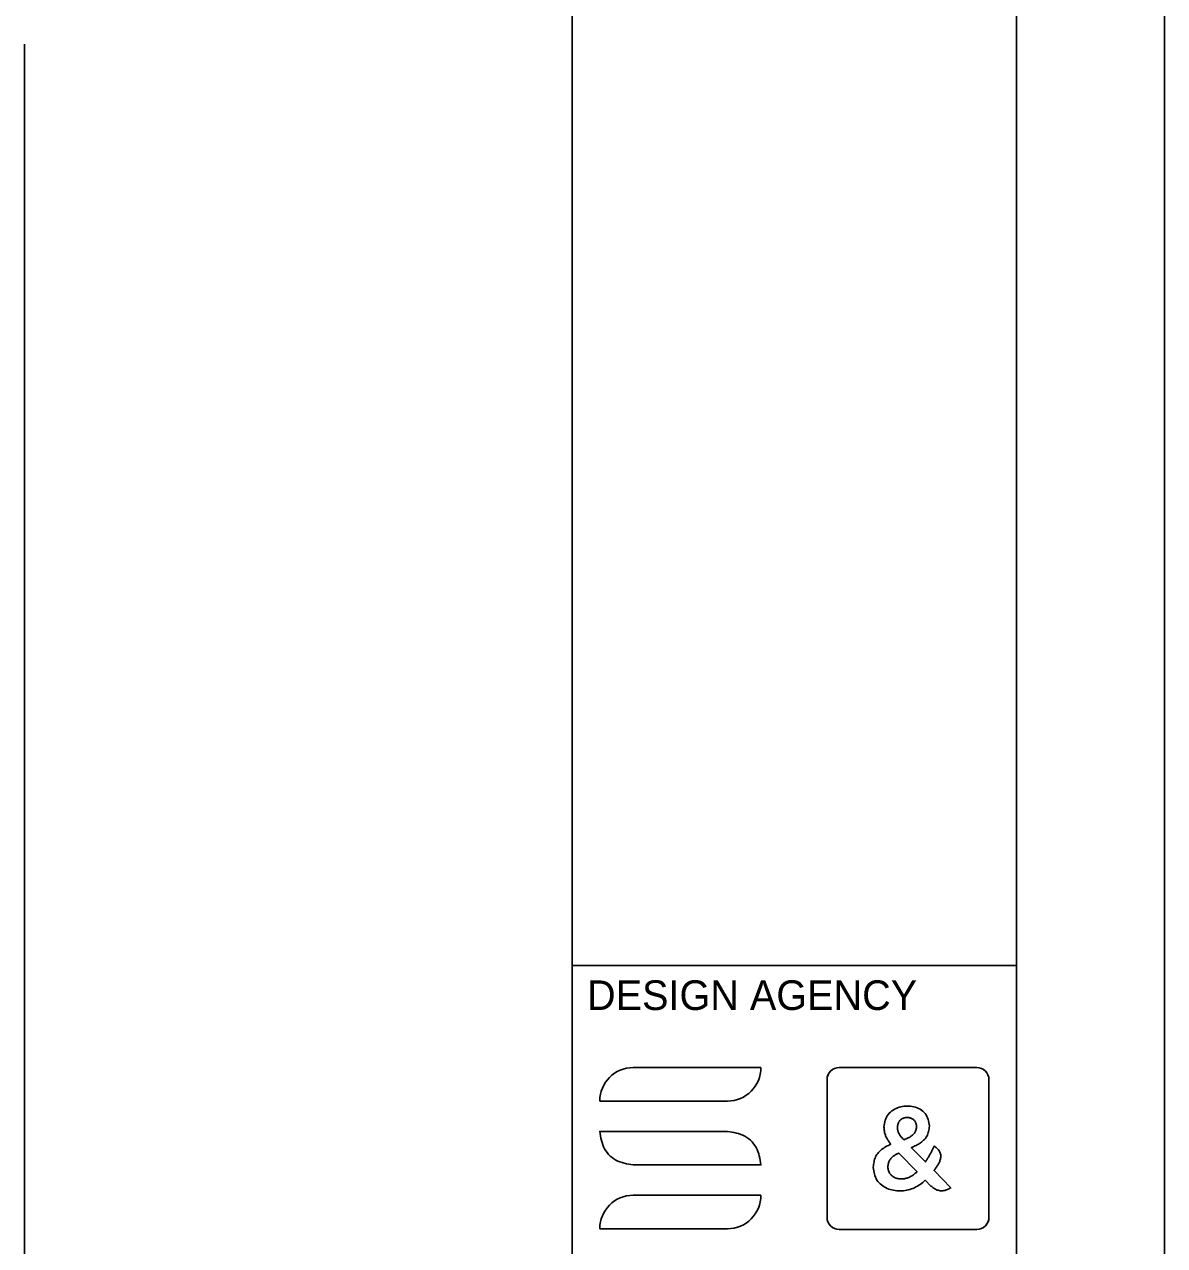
# Model space of a CAD drawing. Extents: x -2280229 to 1306, y -58886 to 440.
# Drawn here: x 603 to 680, y 81.1 to 163.6 of the extents above; entities that cross this region are included whole.
import ezdxf

# ---------------------------------------------------------------- set-up
doc = ezdxf.new("R2010")
doc.units = 0
for name, color, linetype in [('GT_Project_Cells', 7, 'Continuous'), ('GT_Project_Soil_Boring', 7, 'Continuous'), ('GT_Project_Text', 7, 'Continuous'), ('SC_Scratch1', 7, 'Continuous'), ('SC_Scratch5', 7, 'Continuous')]:
    doc.layers.add(name, color=color, linetype=linetype)

msp = doc.modelspace()

# ---------------------------------------------------------------- linework, layer by layer
at = {"layer": 'GT_Project_Soil_Boring'}
for p, q in [((667.315, 93.113), (658.028, 93.113)), ((657.209, 92.294), (657.209, 82.998)), ((668.143, 83.01), (668.143, 92.294)), ((661.968, 89.124), (661.962, 89.074)), ((661.962, 89.074), (661.962, 89.058)), ((661.975, 89.175), (661.968, 89.124)), ((661.983, 89.224), (661.975, 89.175)), ((661.993, 89.273), (661.983, 89.224)), ((662.005, 89.321), (661.993, 89.273)), ((662.021, 89.367), (662.005, 89.321)), ((662.04, 89.412), (662.021, 89.367)), ((662.064, 89.455), (662.04, 89.412)), ((662.093, 89.496), (662.064, 89.455)), ((662.125, 89.535), (662.093, 89.496)), ((662.16, 89.571), (662.125, 89.535)), ((662.198, 89.604), (662.16, 89.571)), ((662.239, 89.634), (662.198, 89.604)), ((662.282, 89.66), (662.239, 89.634)), ((662.327, 89.682), (662.282, 89.66)), ((662.374, 89.7), (662.327, 89.682)), ((662.422, 89.715), (662.374, 89.7)), ((662.47, 89.727), (662.422, 89.715)), ((662.52, 89.735), (662.47, 89.727)), ((662.57, 89.739), (662.52, 89.735)), ((662.62, 89.741), (662.57, 89.739)), ((662.67, 89.739), (662.62, 89.741)), ((662.72, 89.734), (662.67, 89.739)), ((662.769, 89.726), (662.72, 89.734)), ((662.818, 89.715), (662.769, 89.726)), ((662.865, 89.7), (662.818, 89.715)), ((662.912, 89.681), (662.865, 89.7)), ((662.956, 89.658), (662.912, 89.681)), ((662.999, 89.631), (662.956, 89.658)), ((663.04, 89.601), (662.999, 89.631)), ((663.078, 89.567), (663.04, 89.601)), ((663.112, 89.531), (663.078, 89.567)), ((663.143, 89.491), (663.112, 89.531)), ((663.169, 89.45), (663.143, 89.491)), ((663.191, 89.406), (663.169, 89.45)), ((663.208, 89.36), (663.191, 89.406)), ((663.222, 89.312), (663.208, 89.36)), ((663.233, 89.264), (663.222, 89.312)), ((663.241, 89.214), (663.233, 89.264)), ((663.248, 89.164), (663.241, 89.214)), ((663.245, 89.04), (663.255, 89.098)), ((663.255, 89.114), (663.248, 89.164)), ((663.255, 89.098), (663.255, 89.114)), ((661.962, 89.058), (661.965, 89.017)), ((661.965, 89.017), (661.969, 88.975)), ((661.969, 88.975), (661.974, 88.934)), ((661.974, 88.934), (661.98, 88.893)), ((661.98, 88.893), (661.988, 88.853)), ((661.988, 88.853), (661.997, 88.813)), ((661.997, 88.813), (662.009, 88.774)), ((662.009, 88.774), (662.024, 88.736)), ((662.024, 88.736), (662.04, 88.698)), ((662.04, 88.698), (662.059, 88.661)), ((662.059, 88.661), (662.079, 88.625)), ((662.079, 88.625), (662.101, 88.589)), ((662.101, 88.589), (662.124, 88.554)), ((662.124, 88.554), (662.147, 88.52)), ((662.147, 88.52), (662.172, 88.487)), ((662.172, 88.487), (662.197, 88.454)), ((662.197, 88.454), (662.222, 88.421)), ((662.222, 88.421), (662.248, 88.389)), ((662.248, 88.389), (662.274, 88.358)), ((662.274, 88.358), (662.328, 88.295)), ((662.328, 88.295), (662.382, 88.233)), ((662.382, 88.233), (662.487, 88.275)), ((662.487, 88.275), (662.539, 88.297)), ((662.539, 88.297), (662.591, 88.32)), ((662.591, 88.32), (662.643, 88.343)), ((662.643, 88.343), (662.694, 88.367)), ((662.694, 88.367), (662.745, 88.393)), ((662.745, 88.393), (662.795, 88.421)), ((662.795, 88.421), (662.845, 88.45)), ((662.845, 88.45), (662.894, 88.481)), ((662.894, 88.481), (662.942, 88.515)), ((662.942, 88.515), (662.988, 88.551)), ((662.988, 88.551), (663.031, 88.589)), ((663.031, 88.589), (663.072, 88.629)), ((663.072, 88.629), (663.109, 88.673)), ((663.109, 88.673), (663.141, 88.718)), ((663.141, 88.718), (663.168, 88.767)), ((663.168, 88.767), (663.19, 88.818)), ((663.19, 88.818), (663.208, 88.872)), ((663.208, 88.872), (663.223, 88.927)), ((663.223, 88.927), (663.235, 88.983)), ((663.235, 88.983), (663.245, 89.04)), ((661.346, 86.632), (661.335, 86.578)), ((661.359, 86.684), (661.346, 86.632)), ((661.376, 86.735), (661.359, 86.684)), ((661.397, 86.785), (661.376, 86.735)), ((661.421, 86.833), (661.397, 86.785)), ((661.45, 86.879), (661.421, 86.833)), ((661.481, 86.924), (661.45, 86.879)), ((661.516, 86.966), (661.481, 86.924)), ((661.553, 87.007), (661.516, 86.966)), ((661.592, 87.046), (661.553, 87.007)), ((661.633, 87.082), (661.592, 87.046)), ((661.675, 87.116), (661.633, 87.082)), ((661.719, 87.148), (661.675, 87.116)), ((661.764, 87.178), (661.719, 87.148)), ((661.81, 87.207), (661.764, 87.178)), ((661.857, 87.234), (661.81, 87.207)), ((661.904, 87.261), (661.857, 87.234)), ((661.952, 87.286), (661.904, 87.261)), ((662.001, 87.311), (661.952, 87.286)), ((662.049, 87.336), (662.001, 87.311)), ((663.287, 86.075), (662.049, 87.336)), ((661.318, 86.47), (661.311, 86.416)), ((661.311, 86.416), (661.311, 86.4)), ((661.311, 86.4), (661.321, 86.337)), ((661.326, 86.525), (661.318, 86.47)), ((661.321, 86.337), (661.333, 86.274)), ((661.335, 86.578), (661.326, 86.525)), ((661.333, 86.274), (661.345, 86.213)), ((661.345, 86.213), (661.361, 86.152)), ((661.361, 86.152), (661.38, 86.093)), ((661.38, 86.093), (661.403, 86.037)), ((661.403, 86.037), (661.431, 85.983)), ((661.431, 85.983), (661.465, 85.932)), ((661.465, 85.932), (661.504, 85.884)), ((661.504, 85.884), (661.548, 85.84)), ((661.548, 85.84), (661.596, 85.799)), ((661.596, 85.799), (661.647, 85.761)), ((662.838, 85.744), (662.893, 85.774)), ((662.893, 85.774), (662.946, 85.807)), ((662.946, 85.807), (662.997, 85.841)), ((662.997, 85.841), (663.048, 85.877)), ((663.048, 85.877), (663.097, 85.915)), ((663.097, 85.915), (663.145, 85.954)), ((663.145, 85.954), (663.193, 85.993)), ((663.193, 85.993), (663.24, 86.034)), ((663.24, 86.034), (663.287, 86.075)), ((661.647, 85.761), (661.701, 85.727)), ((661.701, 85.727), (661.757, 85.697)), ((661.757, 85.697), (661.815, 85.671)), ((661.815, 85.671), (661.874, 85.649)), ((661.874, 85.649), (661.933, 85.63)), ((661.933, 85.63), (661.994, 85.615)), ((661.994, 85.615), (662.055, 85.604)), ((662.055, 85.604), (662.117, 85.596)), ((662.117, 85.596), (662.179, 85.592)), ((662.179, 85.592), (662.242, 85.591)), ((662.242, 85.591), (662.304, 85.593)), ((662.304, 85.593), (662.366, 85.598)), ((662.366, 85.598), (662.427, 85.606)), ((662.427, 85.606), (662.488, 85.617)), ((662.488, 85.617), (662.549, 85.632)), ((662.549, 85.632), (662.609, 85.649)), ((662.609, 85.649), (662.668, 85.669)), ((662.668, 85.669), (662.726, 85.691)), ((662.726, 85.691), (662.783, 85.717)), ((662.783, 85.717), (662.838, 85.744)), ((658.028, 82.179), (667.32, 82.179))]:
    msp.add_line(p, q, dxfattribs=at)
for points in [[(652.745, 93.113), (644.121, 93.113)], [(657.572, 92.974), (657.556, 92.964), (657.51, 92.931), (657.467, 92.894), (657.427, 92.854), (657.39, 92.811), (657.357, 92.766), (657.347, 92.749)], [(667.32, 93.113), (658.028, 93.113)], [(668.048, 92.668), (668.048, 92.668), (668.023, 92.718), (667.994, 92.765), (667.961, 92.811), (667.924, 92.854), (667.884, 92.894), (667.841, 92.931), (667.795, 92.964), (667.748, 92.994), (667.733, 93.001)], [(657.209, 92.294), (657.209, 82.998)], [(668.143, 82.998), (668.143, 92.294)], [(641.857, 90.849), (650.481, 90.849)], [(661.767, 90.302), (661.869, 90.353), (661.972, 90.396), (662.078, 90.432), (662.186, 90.461), (662.296, 90.483), (662.406, 90.499), (662.518, 90.508), (662.63, 90.511), (662.742, 90.507), (662.853, 90.498), (662.964, 90.481), (663.073, 90.458), (663.18, 90.428), (663.285, 90.39), (663.388, 90.344), (663.487, 90.29), (663.583, 90.228), (663.672, 90.158), (663.755, 90.082), (663.83, 89.999), (663.896, 89.909), (663.951, 89.815), (663.996, 89.715), (664.031, 89.611), (664.06, 89.503), (664.083, 89.393), (664.102, 89.282), (664.121, 89.162), (664.108, 89.064), (664.096, 88.976), (664.081, 88.888), (664.064, 88.801), (664.043, 88.717), (664.017, 88.634), (663.985, 88.553), (663.946, 88.476), (663.9, 88.402), (663.848, 88.331), (663.791, 88.263), (663.729, 88.199), (663.663, 88.139), (663.593, 88.083), (663.522, 88.03), (663.448, 87.981), (663.372, 87.936), (663.295, 87.894), (663.217, 87.854), (663.138, 87.816), (663.059, 87.78), (662.978, 87.744), (662.898, 87.709), (663.85, 86.741), (663.879, 86.786), (663.908, 86.831), (663.937, 86.876), (663.965, 86.921), (663.994, 86.966), (664.022, 87.011), (664.049, 87.057), (664.077, 87.103), (664.103, 87.149), (664.13, 87.195), (664.156, 87.242), (664.181, 87.289), (664.207, 87.336), (664.232, 87.383), (664.256, 87.43), (664.281, 87.477), (664.305, 87.525), (664.328, 87.573), (664.352, 87.621), (664.376, 87.668), (664.399, 87.716), (664.422, 87.764), (664.445, 87.812), (664.492, 87.777), (664.538, 87.742), (664.583, 87.706), (664.627, 87.669), (664.669, 87.629), (664.708, 87.588), (664.744, 87.544), (664.777, 87.497), (664.806, 87.448), (664.831, 87.395), (664.852, 87.34), (664.868, 87.284), (664.88, 87.227), (664.887, 87.169), (664.889, 87.112), (664.886, 87.055), (664.878, 86.998), (664.867, 86.943), (664.852, 86.887), (664.834, 86.833), (664.814, 86.778), (664.793, 86.724), (664.772, 86.669), (664.758, 86.647), (664.735, 86.61), (664.707, 86.565), (664.679, 86.52), (664.651, 86.475), (664.621, 86.43), (664.592, 86.385), (664.562, 86.341), (664.532, 86.297), (664.501, 86.254), (664.47, 86.211), (664.445, 86.176), (664.43, 86.154), (665.559, 84.985), (665.502, 84.956), (665.445, 84.927), (665.388, 84.9), (665.33, 84.874), (665.272, 84.851), (665.212, 84.83), (665.152, 84.814), (665.09, 84.801), (665.027, 84.793), (664.963, 84.79), (664.899, 84.791), (664.835, 84.797), (664.772, 84.808), (664.71, 84.823), (664.649, 84.842), (664.591, 84.865), (664.534, 84.893), (664.48, 84.924), (664.426, 84.957), (664.374, 84.993), (664.323, 85.031), (664.272, 85.07), (664.222, 85.109), (663.842, 85.503), (663.757, 85.431), (663.671, 85.36), (663.584, 85.291), (663.495, 85.224), (663.404, 85.161), (663.31, 85.101), (663.213, 85.047), (663.113, 84.997), (663.011, 84.952), (662.906, 84.912), (662.8, 84.878), (662.692, 84.848), (662.583, 84.825), (662.473, 84.806), (662.363, 84.793), (662.251, 84.784), (662.14, 84.781), (662.028, 84.783), (661.916, 84.79), (661.805, 84.803), (661.695, 84.821), (661.586, 84.845), (661.478, 84.875), (661.371, 84.91), (661.266, 84.953), (661.164, 85.002), (661.063, 85.057), (660.967, 85.119), (660.875, 85.186), (660.79, 85.26), (660.71, 85.34), (660.639, 85.425), (660.576, 85.515), (660.523, 85.61), (660.478, 85.71), (660.441, 85.814), (660.411, 85.921), (660.385, 86.03), (660.364, 86.142), (660.345, 86.255), (660.326, 86.375), (660.337, 86.475), (660.349, 86.566), (660.362, 86.656), (660.378, 86.745), (660.398, 86.832), (660.422, 86.918), (660.452, 87.003), (660.488, 87.084), (660.531, 87.164), (660.579, 87.24), (660.633, 87.313), (660.692, 87.383), (660.754, 87.45), (660.821, 87.513), (660.89, 87.571), (660.962, 87.626), (661.036, 87.677), (661.112, 87.726), (661.189, 87.771), (661.268, 87.815), (661.348, 87.857), (661.428, 87.899), (661.509, 87.939), (661.477, 87.984), (661.444, 88.029), (661.412, 88.074), (661.381, 88.119), (661.35, 88.165), (661.32, 88.211), (661.29, 88.258), (661.262, 88.306), (661.236, 88.354), (661.21, 88.403), (661.186, 88.454), (661.164, 88.504), (661.144, 88.556), (661.126, 88.608), (661.11, 88.661), (661.096, 88.714), (661.085, 88.768), (661.076, 88.823), (661.068, 88.877), (661.062, 88.932), (661.057, 88.987), (661.053, 89.043), (661.048, 89.109), (661.067, 89.226), (661.087, 89.338), (661.11, 89.448), (661.138, 89.555), (661.173, 89.659), (661.217, 89.76), (661.271, 89.855), (661.334, 89.945), (661.407, 90.029), (661.488, 90.108), (661.576, 90.179), (661.67, 90.244), (661.767, 90.302)], [(652.336, 87.846), (652.245, 87.971), (652.143, 88.09), (652.033, 88.2), (651.915, 88.301), (651.789, 88.393), (651.658, 88.473), (651.522, 88.542), (651.381, 88.599), (651.236, 88.647), (651.089, 88.688), (650.939, 88.721), (650.787, 88.751), (650.634, 88.777), (650.481, 88.801), (641.857, 88.801), (641.882, 88.647), (641.908, 88.494), (641.937, 88.343), (641.971, 88.193), (642.011, 88.045), (642.059, 87.901), (642.117, 87.76), (642.185, 87.624), (642.266, 87.493), (642.357, 87.367), (642.459, 87.249), (642.569, 87.138), (642.687, 87.037), (642.813, 86.946), (642.944, 86.865), (643.08, 86.797), (643.221, 86.739), (643.366, 86.691), (643.513, 86.651), (643.663, 86.617), (643.815, 86.588), (643.968, 86.562), (644.121, 86.537), (652.745, 86.537), (652.72, 86.691), (652.694, 86.844), (652.665, 86.996), (652.631, 87.146), (652.591, 87.293), (652.543, 87.437), (652.485, 87.578), (652.417, 87.714), (652.336, 87.846)], [(652.745, 84.489), (644.121, 84.489)], [(641.857, 82.226), (650.481, 82.226)], [(658.028, 82.179), (667.32, 82.179)]]:
    msp.add_lwpolyline(points, dxfattribs=at)
for points in [[(663.842, 85.503), (663.757, 85.431), (663.671, 85.36), (663.584, 85.291), (663.495, 85.224), (663.404, 85.161), (663.31, 85.101), (663.213, 85.047), (663.113, 84.997), (663.011, 84.952), (662.906, 84.912), (662.8, 84.878), (662.692, 84.848), (662.583, 84.825), (662.473, 84.806), (662.363, 84.793), (662.251, 84.784), (662.14, 84.781), (662.028, 84.783), (661.916, 84.79), (661.805, 84.803), (661.695, 84.821), (661.586, 84.845), (661.478, 84.875), (661.371, 84.91), (661.266, 84.953), (661.164, 85.002), (661.063, 85.057), (660.967, 85.119), (660.875, 85.186), (660.79, 85.26), (660.71, 85.34), (660.639, 85.425), (660.576, 85.515), (660.523, 85.61), (660.478, 85.71), (660.441, 85.814), (660.411, 85.921), (660.385, 86.03), (660.364, 86.142), (660.345, 86.255), (660.327, 86.368), (660.327, 86.384), (660.337, 86.475), (660.349, 86.566), (660.362, 86.656), (660.378, 86.745), (660.398, 86.832), (660.422, 86.918), (660.452, 87.003), (660.488, 87.084), (660.531, 87.164), (660.579, 87.24), (660.633, 87.313), (660.692, 87.383), (660.754, 87.45), (660.821, 87.513), (660.89, 87.571), (660.962, 87.626), (661.036, 87.677), (661.112, 87.726), (661.189, 87.771), (661.268, 87.815), (661.348, 87.857), (661.428, 87.899), (661.509, 87.939), (661.477, 87.984), (661.444, 88.029), (661.412, 88.074), (661.381, 88.119), (661.35, 88.165), (661.32, 88.211), (661.29, 88.258), (661.262, 88.306), (661.236, 88.354), (661.21, 88.403), (661.186, 88.454), (661.164, 88.504), (661.144, 88.556), (661.126, 88.608), (661.11, 88.661), (661.096, 88.714), (661.085, 88.768), (661.076, 88.823), (661.068, 88.877), (661.062, 88.932), (661.057, 88.987), (661.053, 89.043), (661.049, 89.098), (661.049, 89.114), (661.067, 89.226), (661.087, 89.338), (661.11, 89.448), (661.138, 89.555), (661.173, 89.659), (661.217, 89.76), (661.271, 89.855), (661.334, 89.945), (661.407, 90.029), (661.488, 90.108), (661.576, 90.179), (661.67, 90.244), (661.767, 90.302), (661.869, 90.353), (661.972, 90.396), (662.078, 90.432), (662.186, 90.461), (662.296, 90.483), (662.406, 90.499), (662.518, 90.508), (662.63, 90.511), (662.742, 90.507), (662.853, 90.498), (662.964, 90.481), (663.073, 90.458), (663.18, 90.428), (663.285, 90.39), (663.388, 90.344), (663.487, 90.29), (663.583, 90.228), (663.672, 90.158), (663.755, 90.082), (663.83, 89.999), (663.896, 89.909), (663.951, 89.815), (663.996, 89.715), (664.031, 89.611), (664.06, 89.503), (664.083, 89.393), (664.102, 89.282), (664.12, 89.169), (664.12, 89.154), (664.108, 89.064), (664.096, 88.976), (664.081, 88.888), (664.064, 88.801), (664.043, 88.717), (664.017, 88.634), (663.985, 88.553), (663.946, 88.476), (663.9, 88.402), (663.848, 88.331), (663.791, 88.263), (663.729, 88.199), (663.663, 88.139), (663.593, 88.083), (663.522, 88.03), (663.448, 87.981), (663.372, 87.936), (663.295, 87.894), (663.217, 87.854), (663.138, 87.816), (663.059, 87.78), (662.978, 87.744), (662.898, 87.709), (663.85, 86.741), (663.879, 86.786), (663.908, 86.831), (663.937, 86.876), (663.965, 86.921), (663.994, 86.966), (664.022, 87.011), (664.049, 87.057), (664.077, 87.103), (664.103, 87.149), (664.13, 87.195), (664.156, 87.242), (664.181, 87.289), (664.207, 87.336), (664.232, 87.383), (664.256, 87.43), (664.281, 87.477), (664.305, 87.525), (664.328, 87.573), (664.352, 87.621), (664.376, 87.668), (664.399, 87.716), (664.422, 87.764), (664.445, 87.812), (664.492, 87.777), (664.538, 87.742), (664.583, 87.706), (664.627, 87.669), (664.669, 87.629), (664.708, 87.588), (664.744, 87.544), (664.777, 87.497), (664.806, 87.448), (664.831, 87.395), (664.852, 87.34), (664.868, 87.284), (664.88, 87.227), (664.887, 87.169), (664.889, 87.112), (664.886, 87.055), (664.878, 86.998), (664.867, 86.943), (664.852, 86.887), (664.834, 86.833), (664.814, 86.778), (664.793, 86.724), (664.772, 86.669), (664.758, 86.647), (664.744, 86.624), (664.729, 86.601), (664.715, 86.578), (664.701, 86.555), (664.687, 86.532), (664.672, 86.509), (664.658, 86.487), (664.643, 86.464), (664.629, 86.442), (664.614, 86.419), (664.599, 86.397), (664.584, 86.374), (664.569, 86.352), (664.554, 86.33), (664.539, 86.308), (664.523, 86.285), (664.508, 86.263), (664.492, 86.242), (664.477, 86.22), (664.461, 86.198), (664.445, 86.176), (664.43, 86.154), (665.559, 84.985), (665.502, 84.956), (665.445, 84.927), (665.388, 84.9), (665.33, 84.874), (665.272, 84.851), (665.212, 84.83), (665.152, 84.814), (665.09, 84.801), (665.027, 84.793), (664.963, 84.79), (664.899, 84.791), (664.835, 84.797), (664.772, 84.808), (664.71, 84.823), (664.649, 84.842), (664.591, 84.865), (664.534, 84.893), (664.48, 84.924), (664.426, 84.957), (664.374, 84.993), (664.323, 85.031), (664.272, 85.07), (664.222, 85.109)], [(663.255, 89.114), (663.248, 89.164), (663.241, 89.214), (663.233, 89.264), (663.222, 89.312), (663.208, 89.36), (663.191, 89.406), (663.169, 89.45), (663.143, 89.491), (663.112, 89.531), (663.078, 89.567), (663.04, 89.601), (662.999, 89.631), (662.956, 89.658), (662.912, 89.681), (662.865, 89.7), (662.818, 89.715), (662.769, 89.726), (662.72, 89.734), (662.67, 89.739), (662.62, 89.741), (662.57, 89.739), (662.52, 89.735), (662.47, 89.727), (662.422, 89.715), (662.374, 89.7), (662.327, 89.682), (662.282, 89.66), (662.239, 89.634), (662.198, 89.604), (662.16, 89.571), (662.125, 89.535), (662.093, 89.496), (662.064, 89.455), (662.04, 89.412), (662.021, 89.367), (662.005, 89.321), (661.993, 89.273), (661.983, 89.224), (661.975, 89.175), (661.968, 89.124), (661.962, 89.074), (661.962, 89.058), (661.965, 89.017), (661.969, 88.975), (661.974, 88.934), (661.98, 88.893), (661.988, 88.853), (661.997, 88.813), (662.009, 88.774), (662.024, 88.736), (662.04, 88.698), (662.059, 88.661), (662.079, 88.625), (662.101, 88.589), (662.124, 88.554), (662.147, 88.52), (662.172, 88.487), (662.197, 88.454), (662.222, 88.421), (662.248, 88.389), (662.274, 88.358), (662.328, 88.295), (662.382, 88.233), (662.487, 88.275), (662.539, 88.297), (662.591, 88.32), (662.643, 88.343), (662.694, 88.367), (662.745, 88.393), (662.795, 88.421), (662.845, 88.45), (662.894, 88.481), (662.942, 88.515), (662.988, 88.551), (663.031, 88.589), (663.072, 88.629), (663.109, 88.673), (663.141, 88.718), (663.168, 88.767), (663.19, 88.818), (663.208, 88.872), (663.223, 88.927), (663.235, 88.983), (663.245, 89.04), (663.255, 89.098)], [(661.311, 86.4), (661.321, 86.337), (661.333, 86.274), (661.345, 86.213), (661.361, 86.152), (661.38, 86.093), (661.403, 86.037), (661.431, 85.983), (661.465, 85.932), (661.504, 85.884), (661.548, 85.84), (661.596, 85.799), (661.647, 85.761), (661.701, 85.727), (661.757, 85.697), (661.815, 85.671), (661.874, 85.649), (661.933, 85.63), (661.994, 85.615), (662.055, 85.604), (662.117, 85.596), (662.179, 85.592), (662.242, 85.591), (662.304, 85.593), (662.366, 85.598), (662.427, 85.606), (662.488, 85.617), (662.549, 85.632), (662.609, 85.649), (662.668, 85.669), (662.726, 85.691), (662.783, 85.717), (662.838, 85.744), (662.893, 85.774), (662.946, 85.807), (662.997, 85.841), (663.048, 85.877), (663.097, 85.915), (663.145, 85.954), (663.193, 85.993), (663.24, 86.034), (663.287, 86.075), (662.049, 87.336), (662.001, 87.311), (661.952, 87.286), (661.904, 87.261), (661.857, 87.234), (661.81, 87.207), (661.764, 87.178), (661.719, 87.148), (661.675, 87.116), (661.633, 87.082), (661.592, 87.046), (661.553, 87.007), (661.516, 86.966), (661.481, 86.924), (661.45, 86.879), (661.421, 86.833), (661.397, 86.785), (661.376, 86.735), (661.359, 86.684), (661.346, 86.632), (661.335, 86.578), (661.326, 86.525), (661.318, 86.47), (661.311, 86.416)]]:
    msp.add_lwpolyline(points, close=True, dxfattribs=at)
for centre, radius, start, end in [((644.121, 90.849), 2.264, 90, 180), ((650.481, 93.113), 2.264, 270, 360), ((658.028, 92.294), 0.819, 90.00569, 180), ((658.028, 92.294), 0.819, 89.99431, 180), ((667.317, 92.288), 0.825, 0.41982, 90.16819), ((667.317, 92.288), 0.825, 0.41982, 89.83181), ((644.121, 82.226), 2.264, 90, 180), ((650.481, 84.489), 2.264, 270, 360), ((658.028, 82.998), 0.819, 180, 270.00569), ((658.028, 82.998), 0.819, 180, 270.00569), ((667.317, 83.004), 0.825, 270.16819, 0.41982), ((667.317, 83.004), 0.825, 270.16819, 359.58018)]:
    msp.add_arc(centre, radius, start, end, dxfattribs=at)
at = {"layer": 'GT_Project_Text'}
msp.add_lwpolyline([(0, 0), (680, 0), (680, 440), (0, 440)], close=True, dxfattribs=at)
at = {"layer": 'SC_Scratch1'}
for p, q in [((640, 10), (640, 430)), ((640, 100), (670, 100))]:
    msp.add_line(p, q, dxfattribs=at)
msp.add_lwpolyline([(30, 430), (670, 430), (670, 10), (30, 10)], close=True, dxfattribs=at)
at = {"layer": 'SC_Scratch5'}
msp.add_line((603.007, 21.221), (603.007, 162.208), dxfattribs=at)

# ---------------------------------------------------------------- texts
at = {"layer": 'GT_Project_Cells'}
msp.add_text('DESIGN AGENCY', height=2, dxfattribs=at).set_placement((641, 97))

doc.saveas('drawing.dxf')
